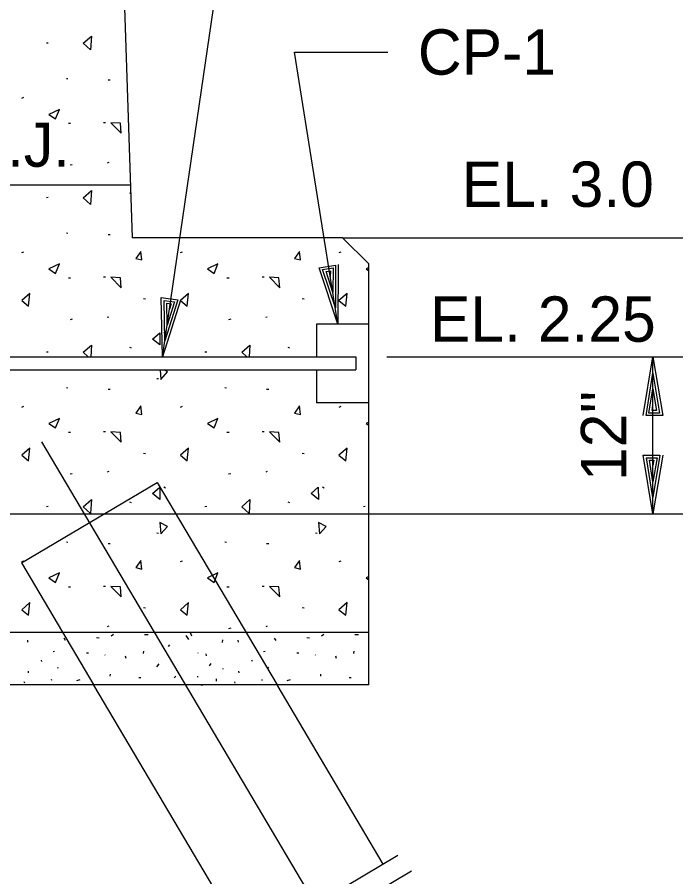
# Model space of a CAD drawing. Extents: x 44742.55 to 44745.38, y 44738.95 to 44741.13.
# Drawn here: x 44743.1188 to 44743.2499, y 44740.3401 to 44740.5111 of the extents above; entities that cross this region are included whole.
import ezdxf

# ---------------------------------------------------------------- set-up
doc = ezdxf.new("R2010")
doc.units = 0
for name, color, linetype in [('G-ANNO-PATT', 7, 'Continuous'), ('Level 1', 7, 'Continuous'), ('Level 10', 7, 'Continuous'), ('Level 2', 7, 'Continuous'), ('Level 3', 7, 'Continuous'), ('Level 4', 7, 'Continuous'), ('S-ANNO-DIMS', 7, 'Continuous')]:
    doc.layers.add(name, color=color, linetype=linetype)

msp = doc.modelspace()

# ---------------------------------------------------------------- linework, layer by layer
at = {"layer": 'G-ANNO-PATT'}
for p, q in [((44743.12497024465, 44740.50595265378), (44743.12462649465, 44740.50592140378)), ((44743.12891555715, 44740.49880421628), (44743.12860305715, 44740.49885890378)), ((44743.13732180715, 44740.49853859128), (44743.13689993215, 44740.49853859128)), ((44743.12007180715, 44740.49512452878), (44743.11969680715, 44740.49493702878)), ((44743.12941555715, 44740.48993702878), (44743.12899368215, 44740.48993702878)), ((44743.13641555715, 44740.490085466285), (44743.13601711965, 44740.490085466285)), ((44743.13703274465, 44740.482179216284), (44743.13672805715, 44740.48206202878)), ((44743.12975149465, 44740.48175734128), (44743.12932961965, 44740.48164015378)), ((44743.14139211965, 44740.47603077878), (44743.14120461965, 44740.47611671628)), ((44743.12891555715, 44740.46806202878), (44743.12860305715, 44740.46811671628)), ((44743.13732180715, 44740.467796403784), (44743.13689993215, 44740.467796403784)), ((44743.12007180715, 44740.464382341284), (44743.11969680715, 44740.46419484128)), ((44743.18319680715, 44740.464382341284), (44743.18282180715, 44740.46419484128)), ((44743.12941555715, 44740.45919484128), (44743.12899368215, 44740.45919484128)), ((44743.13641555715, 44740.45934327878), (44743.13601711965, 44740.45934327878)), ((44743.16097805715, 44740.45919484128), (44743.16055618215, 44740.45919484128)), ((44743.16797805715, 44740.45934327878), (44743.16757961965, 44740.45934327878)), ((44743.14436868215, 44740.45497609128), (44743.14396243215, 44740.45504640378)), ((44743.17593118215, 44740.45497609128), (44743.17552493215, 44740.45504640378)), ((44743.18213430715, 44740.453241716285), (44743.18213430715, 44740.453241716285)), ((44743.13703274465, 44740.45143702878), (44743.13672805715, 44740.45131984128)), ((44743.16859524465, 44740.45143702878), (44743.16829055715, 44740.45131984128)), ((44743.12975149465, 44740.45101515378), (44743.12932961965, 44740.45089796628)), ((44743.16131399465, 44740.45101515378), (44743.16089211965, 44740.45089796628)), ((44743.14834524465, 44740.44812452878), (44743.14799368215, 44740.44833546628)), ((44743.14818899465, 44740.44672609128), (44743.14818899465, 44740.44672609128)), ((44743.12497024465, 44740.44446827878), (44743.12462649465, 44740.44443702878)), ((44743.14154055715, 44740.44521827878), (44743.14120461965, 44740.44537452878)), ((44743.15653274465, 44740.44446827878), (44743.15618899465, 44740.44443702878)), ((44743.173103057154, 44740.44521827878), (44743.17276711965, 44740.44537452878)), ((44743.147720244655, 44740.44350734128), (44743.147720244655, 44740.44350734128)), ((44743.14693899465, 44740.43914796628), (44743.14662649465, 44740.439171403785)), ((44743.12891555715, 44740.43731984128), (44743.12860305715, 44740.43737452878)), ((44743.13732180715, 44740.43705421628), (44743.13689993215, 44740.43705421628)), ((44743.16047805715, 44740.43731984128), (44743.16016555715, 44740.43737452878)), ((44743.16888430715, 44740.43705421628), (44743.16846243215, 44740.43705421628)), ((44743.12007180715, 44740.43364015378), (44743.11969680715, 44740.43345265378)), ((44743.15163430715, 44740.43364015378), (44743.15125930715, 44740.43345265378)), ((44743.12941555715, 44740.42845265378), (44743.12899368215, 44740.42845265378)), ((44743.13641555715, 44740.428601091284), (44743.13601711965, 44740.428601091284)), ((44743.16097805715, 44740.42845265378), (44743.16055618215, 44740.42845265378)), ((44743.16797805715, 44740.428601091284), (44743.16757961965, 44740.428601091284)), ((44743.14436868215, 44740.42423390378), (44743.14396243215, 44740.42430421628)), ((44743.17593118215, 44740.42423390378), (44743.17552493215, 44740.42430421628)), ((44743.13703274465, 44740.42069484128), (44743.13672805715, 44740.42057765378)), ((44743.16859524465, 44740.42069484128), (44743.16829055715, 44740.42057765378)), ((44743.12975149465, 44740.42027296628), (44743.12932961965, 44740.42015577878)), ((44743.16131399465, 44740.42027296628), (44743.16089211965, 44740.42015577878)), ((44743.14834524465, 44740.41738234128), (44743.14799368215, 44740.417593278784)), ((44743.17990774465, 44740.41738234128), (44743.17955618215, 44740.417593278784)), ((44743.12497024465, 44740.41372609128), (44743.12462649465, 44740.41369484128)), ((44743.14154055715, 44740.41447609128), (44743.14120461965, 44740.41463234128)), ((44743.15653274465, 44740.41372609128), (44743.15618899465, 44740.41369484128)), ((44743.173103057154, 44740.41447609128), (44743.17276711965, 44740.41463234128)), ((44743.14693899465, 44740.408405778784), (44743.14662649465, 44740.40842921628)), ((44743.17850149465, 44740.408405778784), (44743.17818899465, 44740.40842921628)), ((44743.12891555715, 44740.40657765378), (44743.12860305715, 44740.406632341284)), ((44743.13732180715, 44740.40631202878), (44743.13689993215, 44740.40631202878)), ((44743.16047805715, 44740.40657765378), (44743.16016555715, 44740.406632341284)), ((44743.16888430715, 44740.40631202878), (44743.16846243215, 44740.40631202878)), ((44743.12007180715, 44740.40289796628), (44743.11969680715, 44740.40271046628)), ((44743.15163430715, 44740.40289796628), (44743.15125930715, 44740.40271046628)), ((44743.18319680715, 44740.40289796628), (44743.18282180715, 44740.40271046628)), ((44743.12941555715, 44740.397710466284), (44743.12899368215, 44740.397710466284)), ((44743.13641555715, 44740.39785890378), (44743.13601711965, 44740.39785890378)), ((44743.16097805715, 44740.397710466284), (44743.16055618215, 44740.397710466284)), ((44743.16797805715, 44740.39785890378), (44743.16757961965, 44740.39785890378)), ((44743.14436868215, 44740.393491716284), (44743.14396243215, 44740.39356202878)), ((44743.17593118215, 44740.393491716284), (44743.17552493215, 44740.39356202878)), ((44743.13703274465, 44740.38995265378), (44743.13672805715, 44740.38983546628)), ((44743.16859524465, 44740.38995265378), (44743.16829055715, 44740.38983546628)), ((44743.13752493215, 44740.388030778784), (44743.13796243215, 44740.38836671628)), ((44743.144165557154, 44740.38830421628), (44743.14485305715, 44740.38831202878)), ((44743.152954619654, 44740.38731202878), (44743.15244680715, 44740.38805421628)), ((44743.15321243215, 44740.38871046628), (44743.153493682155, 44740.388030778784)), ((44743.16131399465, 44740.38953077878), (44743.16089211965, 44740.38941359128)), ((44743.17939993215, 44740.388030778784), (44743.17983743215, 44740.38836671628)), ((44743.18604055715, 44740.38830421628), (44743.18672024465, 44740.38831202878)), ((44743.120954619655, 44740.386741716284), (44743.120907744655, 44740.38717921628)), ((44743.12846243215, 44740.38710890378), (44743.128181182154, 44740.38752296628)), ((44743.13510305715, 44740.38756202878), (44743.13458743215, 44740.38764015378)), ((44743.15966555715, 44740.38720265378), (44743.15957961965, 44740.38671046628)), ((44743.16282961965, 44740.386741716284), (44743.16278274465, 44740.38717921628)), ((44743.17033743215, 44740.38710890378), (44743.17005618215, 44740.38752296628)), ((44743.17697805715, 44740.38756202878), (44743.17645461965, 44740.38764015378)), ((44743.12595461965, 44740.38489796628), (44743.12625930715, 44740.38499171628)), ((44743.13259524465, 44740.384616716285), (44743.132978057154, 44740.38462452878)), ((44743.14397024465, 44740.38499171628), (44743.14386868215, 44740.38449171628)), ((44743.14893118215, 44740.38587452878), (44743.14919680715, 44740.38620265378)), ((44743.15479836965, 44740.38464796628), (44743.15482961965, 44740.38460109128)), ((44743.167829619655, 44740.38489796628), (44743.168134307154, 44740.38499171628)), ((44743.17446243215, 44740.384616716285), (44743.17485305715, 44740.38462452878)), ((44743.185845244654, 44740.38499171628), (44743.18574368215, 44740.38449171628)), ((44743.123743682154, 44740.382929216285), (44743.12364993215, 44740.383147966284)), ((44743.13633743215, 44740.38414796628), (44743.13623586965, 44740.38423390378)), ((44743.140485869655, 44740.38352296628), (44743.140345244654, 44740.38396046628)), ((44743.15647805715, 44740.38405421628), (44743.15645461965, 44740.38446046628)), ((44743.16561868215, 44740.382929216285), (44743.16552493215, 44740.383147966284)), ((44743.178212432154, 44740.38414796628), (44743.17811086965, 44740.38423390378)), ((44743.18235305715, 44740.38352296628), (44743.18222024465, 44740.38396046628)), ((44743.12691555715, 44740.38156984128), (44743.12700149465, 44740.38178859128)), ((44743.146603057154, 44740.381866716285), (44743.147056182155, 44740.38246827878)), ((44743.15711868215, 44740.38202296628), (44743.15744680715, 44740.38250734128)), ((44743.15979836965, 44740.38136671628), (44743.15982180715, 44740.38154640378)), ((44743.16879055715, 44740.38156984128), (44743.16887649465, 44740.38178859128)), ((44743.12109524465, 44740.38063234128), (44743.12104836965, 44740.38096046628)), ((44743.15004055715, 44740.37963234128), (44743.150376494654, 44740.38001515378)), ((44743.15482961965, 44740.37988234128), (44743.15462649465, 44740.37984327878)), ((44743.158509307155, 44740.37901515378), (44743.15849368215, 44740.37947609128)), ((44743.16297024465, 44740.38063234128), (44743.16291555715, 44740.38096046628)), ((44743.17922024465, 44740.37998390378), (44743.17924368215, 44740.38038234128)), ((44743.18489993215, 44740.379733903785), (44743.185313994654, 44740.37974171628)), ((44743.12032180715, 44740.378624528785), (44743.120235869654, 44740.37885890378)), ((44743.125696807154, 44740.37914015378), (44743.12566555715, 44740.37935890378)), ((44743.130673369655, 44740.37910109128), (44743.13132961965, 44740.37932765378)), ((44743.15536086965, 44740.37824171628), (44743.15578274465, 44740.37827296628)), ((44743.16219680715, 44740.378624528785), (44743.16211086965, 44740.37885890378)), ((44743.167563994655, 44740.37914015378), (44743.16754055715, 44740.37935890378)), ((44743.17254836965, 44740.37910109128), (44743.17320461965, 44740.37932765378))]:
    msp.add_line(p, q, dxfattribs=at)
for points in [[(44743.13341555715, 44740.50457765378), (44743.13197024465, 44740.50591359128), (44743.13357180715, 44740.50734327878)], [(44743.12646243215, 44740.49085109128), (44743.127204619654, 44740.49276515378), (44743.12513430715, 44740.49175734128)], [(44743.13934524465, 44740.48998390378), (44743.13747024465, 44740.490085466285), (44743.139501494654, 44740.48800734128)], [(44743.13341555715, 44740.473835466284), (44743.13197024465, 44740.475171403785), (44743.13357180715, 44740.47660109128)], [(44743.143634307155, 44740.46279640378), (44743.143415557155, 44740.46450734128), (44743.14245461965, 44740.46307765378)], [(44743.175196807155, 44740.46279640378), (44743.174978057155, 44740.46450734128), (44743.17401711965, 44740.46307765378)], [(44743.12646243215, 44740.46010890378), (44743.127204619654, 44740.46202296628), (44743.12513430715, 44740.46101515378)], [(44743.15802493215, 44740.46010890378), (44743.158767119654, 44740.46202296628), (44743.15669680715, 44740.46101515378)], [(44743.13934524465, 44740.45924171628), (44743.13747024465, 44740.45934327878), (44743.139501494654, 44740.45726515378)], [(44743.17090774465, 44740.45924171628), (44743.16903274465, 44740.45934327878), (44743.171063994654, 44740.45726515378)], [(44743.12133743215, 44740.45610109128), (44743.11973586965, 44740.454702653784), (44743.12106399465, 44740.45358546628)], [(44743.18446243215, 44740.45610109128), (44743.18286086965, 44740.454702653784), (44743.18418899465, 44740.45358546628)], [(44743.14723586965, 44740.445913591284), (44743.14573586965, 44740.44704640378), (44743.14717336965, 44740.44831984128)], [(44743.143634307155, 44740.43205421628), (44743.143415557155, 44740.43376515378), (44743.14245461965, 44740.432335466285)], [(44743.175196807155, 44740.43205421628), (44743.174978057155, 44740.43376515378), (44743.17401711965, 44740.432335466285)], [(44743.12646243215, 44740.42936671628), (44743.127204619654, 44740.43128077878), (44743.12513430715, 44740.43027296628)], [(44743.15802493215, 44740.42936671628), (44743.158767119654, 44740.43128077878), (44743.15669680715, 44740.43027296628)], [(44743.13934524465, 44740.42849952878), (44743.13747024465, 44740.428601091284), (44743.139501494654, 44740.42652296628)], [(44743.17090774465, 44740.42849952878), (44743.16903274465, 44740.428601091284), (44743.171063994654, 44740.42652296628)], [(44743.12133743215, 44740.42535890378), (44743.11973586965, 44740.42396046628), (44743.12106399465, 44740.42284327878)], [(44743.15289993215, 44740.42535890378), (44743.15129836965, 44740.42396046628), (44743.15262649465, 44740.42284327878)], [(44743.18446243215, 44740.42535890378), (44743.18286086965, 44740.42396046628), (44743.18418899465, 44740.42284327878)], [(44743.14723586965, 44740.41517140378), (44743.14573586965, 44740.41630421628), (44743.14717336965, 44740.41757765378)], [(44743.17879836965, 44740.41517140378), (44743.17729836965, 44740.41630421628), (44743.17873586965, 44740.41757765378)], [(44743.13341555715, 44740.41235109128), (44743.13197024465, 44740.413687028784), (44743.13357180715, 44740.41511671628)], [(44743.16497805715, 44740.41235109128), (44743.16353274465, 44740.413687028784), (44743.16513430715, 44740.41511671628)], [(44743.14739211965, 44740.40829640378), (44743.14872805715, 44740.40979640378), (44743.14723586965, 44740.41059327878)], [(44743.17895461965, 44740.40829640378), (44743.18029055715, 44740.40979640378), (44743.17879836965, 44740.41059327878)], [(44743.143634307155, 44740.40131202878), (44743.143415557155, 44740.40302296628), (44743.14245461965, 44740.40159327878)], [(44743.175196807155, 44740.40131202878), (44743.174978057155, 44740.40302296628), (44743.17401711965, 44740.40159327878)], [(44743.12646243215, 44740.39862452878), (44743.127204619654, 44740.40053859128), (44743.12513430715, 44740.399530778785)], [(44743.15802493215, 44740.39862452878), (44743.158767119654, 44740.40053859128), (44743.15669680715, 44740.399530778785)], [(44743.13934524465, 44740.397757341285), (44743.13747024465, 44740.39785890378), (44743.139501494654, 44740.39578077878)], [(44743.17090774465, 44740.397757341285), (44743.16903274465, 44740.39785890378), (44743.171063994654, 44740.39578077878)], [(44743.12133743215, 44740.39461671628), (44743.11973586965, 44740.39321827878), (44743.12106399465, 44740.39210109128)], [(44743.15289993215, 44740.39461671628), (44743.15129836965, 44740.39321827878), (44743.15262649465, 44740.39210109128)], [(44743.18446243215, 44740.39461671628), (44743.18286086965, 44740.39321827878), (44743.18418899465, 44740.39210109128)]]:
    msp.add_lwpolyline(points, close=True, dxfattribs=at)
for points in [[(44743.13297024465, 44740.44350734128), (44743.13197024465, 44740.44442921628), (44743.13357180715, 44740.44585890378), (44743.13343899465, 44740.44350734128)], [(44743.16453274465, 44740.44350734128), (44743.16353274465, 44740.44442921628), (44743.16513430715, 44740.44585890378), (44743.16500149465, 44740.44350734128)], [(44743.14726711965, 44740.44090577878), (44743.14739211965, 44740.439038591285)], [(44743.14739211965, 44740.439038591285), (44743.14872805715, 44740.44053859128), (44743.14804055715, 44740.44090577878)], [(44743.18879055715, 44740.39978859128), (44743.18825930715, 44740.399530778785), (44743.18879055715, 44740.399171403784)]]:
    msp.add_lwpolyline(points, dxfattribs=at)
at = {"layer": 'Level 1'}
for p, q in [((44743.12497024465, 44740.475210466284), (44743.12462649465, 44740.47517921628)), ((44743.15163430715, 44740.464382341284), (44743.15125930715, 44740.46419484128)), ((44743.18264211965, 44740.45003077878), (44743.18264211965, 44740.45003077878)), ((44743.24534524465, 44740.44350734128), (44743.24534524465, 44740.44350734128)), ((44743.24534524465, 44740.44025734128), (44743.24534524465, 44740.44025734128)), ((44743.18319680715, 44740.43364015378), (44743.18282180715, 44740.43345265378)), ((44743.123657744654, 44740.42663234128), (44743.20589993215, 44740.28773390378)), ((44743.24534524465, 44740.41551515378), (44743.24534524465, 44740.41551515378)), ((44743.18809524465, 44740.41372609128), (44743.187751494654, 44740.41369484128)), ((44743.24534524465, 44740.412265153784), (44743.24534524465, 44740.412265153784)), ((44743.13734524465, 44740.37998390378), (44743.13736868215, 44740.38038234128)), ((44743.14302493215, 44740.379733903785), (44743.14344680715, 44740.37974171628)), ((44743.19454055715, 44740.34428077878), (44743.175860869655, 44740.33321827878)), ((44743.197259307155, 44740.34118702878), (44743.17793899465, 44740.32974171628))]:
    msp.add_line(p, q, dxfattribs=at)
for points in [[(44743.18879055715, 44740.461272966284), (44743.18825930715, 44740.46101515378), (44743.18879055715, 44740.460655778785)], [(44743.18879055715, 44740.43053077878), (44743.18825930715, 44740.43027296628), (44743.18879055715, 44740.42991359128)]]:
    msp.add_lwpolyline(points, dxfattribs=at)
msp.add_lwpolyline([(44743.15289993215, 44740.45610109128), (44743.15129836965, 44740.454702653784), (44743.15262649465, 44740.45358546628)], close=True, dxfattribs=at)
at = {"layer": 'Level 10'}
for p, q in [((44743.12615774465, 44740.93288234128), (44743.141681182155, 44740.46721827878)), ((44743.18357180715, 44740.46721827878), (44743.141681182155, 44740.46721827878)), ((44743.18357180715, 44740.46721827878), (44743.18879055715, 44740.46200734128)), ((44743.18879055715, 44740.37824171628), (44743.18879055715, 44740.46200734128)), ((44743.18879055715, 44740.38871046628), (44743.071017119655, 44740.38871046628)), ((44743.18879055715, 44740.37824171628), (44743.071017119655, 44740.37824171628))]:
    msp.add_line(p, q, dxfattribs=at)
at = {"layer": 'Level 2'}
for p, q in [((44743.141329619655, 44740.47768702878), (44743.09457180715, 44740.47768702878)), ((44743.18879055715, 44740.45003077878), (44743.17836086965, 44740.45003077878)), ((44743.17836086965, 44740.45003077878), (44743.17836086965, 44740.44350734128)), ((44743.07622805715, 44740.44350734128), (44743.18618118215, 44740.44350734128)), ((44743.18618118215, 44740.44350734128), (44743.18618118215, 44740.44090577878)), ((44743.192376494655, 44740.44350734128), (44743.25613430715, 44740.44350734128)), ((44743.07622805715, 44740.44090577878), (44743.18618118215, 44740.44090577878)), ((44743.17836086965, 44740.44090577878), (44743.17836086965, 44740.43439015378)), ((44743.18879055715, 44740.43439015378), (44743.17836086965, 44740.43439015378)), ((44743.11968118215, 44740.40251515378), (44743.14670461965, 44740.41851515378)), ((44743.14670461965, 44740.41851515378), (44743.17056399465, 44740.37824171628)), ((44743.078962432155, 44740.412265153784), (44743.25613430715, 44740.412265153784)), ((44743.11968118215, 44740.40251515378), (44743.134095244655, 44740.378179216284)), ((44743.16465774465, 44740.32657765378), (44743.134095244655, 44740.378179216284)), ((44743.19167336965, 44740.342577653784), (44743.17056399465, 44740.37824171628))]:
    msp.add_line(p, q, dxfattribs=at)
at = {"layer": 'Level 3'}
msp.add_line((44743.18357180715, 44740.46721827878), (44743.35678274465, 44740.46721827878), dxfattribs=at)
at = {"layer": 'S-ANNO-DIMS'}
msp.add_line((44743.24534524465, 44740.412265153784), (44743.24534524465, 44740.44350734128), dxfattribs=at)
for points in [[(44743.147720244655, 44740.44350734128), (44743.16238430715, 44740.543835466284), (44743.18090774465, 44740.543835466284)], [(44743.18264211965, 44740.45003077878), (44743.17402493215, 44740.504155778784), (44743.192548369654, 44740.504155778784)], [(44743.18272024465, 44740.46187452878), (44743.18264211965, 44740.45003077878), (44743.17889211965, 44740.46126515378), (44743.182165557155, 44740.46178859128), (44743.18213430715, 44740.453241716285), (44743.179587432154, 44740.460874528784), (44743.18168899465, 44740.46121046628), (44743.18164211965, 44740.45632765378), (44743.18028274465, 44740.460476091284), (44743.18114993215, 44740.46061671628), (44743.18112649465, 44740.45953859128)], [(44743.15132961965, 44740.45478859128), (44743.147720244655, 44740.44350734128), (44743.147493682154, 44740.45535109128), (44743.15077493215, 44740.45487452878), (44743.14818899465, 44740.44672609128), (44743.14804055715, 44740.45476515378), (44743.15014211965, 44740.45446046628), (44743.14864211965, 44740.44981202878), (44743.14858743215, 44740.45417921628), (44743.149454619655, 44740.45405421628), (44743.14911086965, 44740.45303077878)], [(44743.24340774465, 44740.43181984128), (44743.24534524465, 44740.44350734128), (44743.247282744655, 44740.43181984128), (44743.24397024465, 44740.43181984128), (44743.24534524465, 44740.44025734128), (44743.246657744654, 44740.43231984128), (44743.244532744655, 44740.43231984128), (44743.24534524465, 44740.43713234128), (44743.24603274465, 44740.432819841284), (44743.245157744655, 44740.432819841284), (44743.24534524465, 44740.43388234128)], [(44743.247282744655, 44740.42395265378), (44743.24534524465, 44740.412265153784), (44743.24340774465, 44740.42395265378), (44743.24672024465, 44740.42395265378), (44743.24534524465, 44740.41551515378), (44743.24403274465, 44740.423452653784), (44743.24615774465, 44740.423452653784), (44743.24534524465, 44740.41864015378), (44743.24465774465, 44740.42295265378), (44743.24553274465, 44740.42295265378), (44743.24534524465, 44740.42189015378)]]:
    msp.add_lwpolyline(points, dxfattribs=at)

# ---------------------------------------------------------------- texts
at = {"layer": 'Level 2'}
msp.add_text('C.J.', height=0.008773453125, dxfattribs=at).set_placement((44743.108392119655, 44740.48134327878))
at = {"layer": 'Level 4'}
for s, p in [('CP-1', (44743.19856399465, 44740.49966359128)), ('EL. 3.0', (44743.20730618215, 44740.47336671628)), ('EL. 2.25', (44743.20097024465, 44740.44653077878))]:
    msp.add_text(s, height=0.00902027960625, dxfattribs=at).set_placement(p)
msp.add_text("12''", height=0.00902027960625, rotation=90, dxfattribs=at).set_placement((44743.24002079, 44740.41881447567))

doc.saveas('drawing.dxf')
